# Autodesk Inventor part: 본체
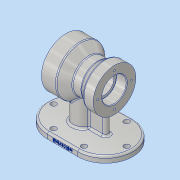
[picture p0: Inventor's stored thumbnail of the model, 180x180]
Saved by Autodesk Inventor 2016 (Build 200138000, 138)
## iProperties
Created: 2020-01
Part Number: 본체
Material: 알루미늄 6061
Document SubType Name: Modeling
Designer: woori
Density: 2.7 g/cm^3
Appearance: 알루미늄 - 평지
Mass: 934.233 g
Surface Area: 654.734 cm^2
Volume: 346.012 cm^3
Author: woori
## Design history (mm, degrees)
sketch "스케치3"
  geometry: L1 (-70, 0)-(-25, 0); L2 (-25, 0)-(25, 0); L3 (25, 0)-(70, 0); L4 (-70, 0)-(-70, 10); L5 (-70, 10)-(70, 10); L6 (70, 10)-(70, 0); 2 further points
  constraints: 12 end point, 2 perpendicular, 2 point on line, 1 coincident, 1 horizontal, 1 midpoint, 1 vertical
  dimensions: "d10" = 45 distance of L1.start L1.end; "d11" = 50 distance of L1.end L2.end; "d12" = 45 distance of L2.end L3.end; "d13" = 10 distance of L1.start L4.end
extrude "돌출1" new body sketch "스케치3" stored distance "d14" = 90; taper "d15" = 0 deg
fillet "모깎기1" dims "d16" = 45
sketch "스케치4"
  geometry: L1 (-40, 80)-(143.887, 80); L2 (-40, 80)-(-40, 120); L3 (-40, 120)-(-16, 120); L4 (40, 115)-(40, 80); L5 (24, 115)-(40, 115); L6 (40, 115)-(40, 80); L7 (-40, 120)-(-16, 120); L8 (-61.291, 80)-(69.038, 80); L9 (-16, 120)-(-1.103, 107.5); L10 (-16, 120)-(3.447, 120); L11 (24, 115)-(44.887, 115); L12 (24, 115)-(13.289, 107.5); L13 (-1.103, 107.5)-(13.289, 107.5); L14 (-25, 0)-(-25, 0) reference; L15 (-25, 0)-(-25, 10) reference; L16 (-25, 10)-(-25, 10) reference; L17 (-25, 10)-(-25, 0) reference; L18 (-70, 10)-(-70, 0) reference; L19 (-70, 10)-(-70, 0) reference; L20 (-70, 10)-(-70, 0) reference; L21 (-25, 0)-(25, 0) reference; 1 further point
  constraints: 26 end point, 4 horizontal, 2 point on line, 1 equal length, 1 parallel, 1 vertical
  dimensions: "d22" = 24 distance of L3.end L2.end; "d25" = 40 deg angle of L9 L10; "d27" = 145 deg angle of L13 L12; "d31" = 30 distance between parallel lines of L18 L2; "d32" = 80 distance between parallel lines of L21 L1; "d33" = 80 distance between parallel lines of L4 L2; "d34" = 16 distance of L5.start L4.start; "d35" = 55 diameter of L13 L1; "d37" = 70 diameter of L5 L1; "d38" = 80 diameter of L3 L1
revolve "회전1" sketch "스케치4" stored, may be unused: angle "d29" = 90 deg
sketch "스케치5"
  geometry: L1 (-49.461, 80)-(59.544, 80); L2 (-40, 40)-(-40, 120) reference; L3 (-40, 80)-(-20, 80); L4 (-20, 80)-(-20, 106); L5 (-20, 106)-(-40, 106); L6 (-40, 106)-(-40, 80); L7 (-20, 80)-(23, 80); L8 (23, 80)-(23, 96); L9 (23, 96)-(-20, 96); L10 (-20, 96)-(-20, 80); L11 (40, 45)-(40, 115) reference; L12 (40, 80)-(23, 80); L13 (23, 80)-(23, 100); L14 (23, 100)-(40, 100); L15 (40, 100)-(40, 80); L16 (-40, 120)-(-16, 120) reference; L17 (-40, 40)-(-16, 40) reference; L18 (24, 115)-(40, 115) reference; L19 (24, 45)-(40, 45) reference; L20 (70, 0)-(25, 0) reference; 1 further point
  constraints: 26 end point, 6 parallel, 4 horizontal, 3 perpendicular, 2 midpoint, 1 point on line
  dimensions: "d39" = 20 distance of L5.end L4.end; "d41" = 52 diameter of L5 L1; "d43" = 17 distance of L13.end L14.end; "d45" = 40 diameter of L14 L1; "d46" = 32 diameter of L9 L1; "d47" = 80 distance between parallel lines of L20 L1
revolve "회전2" sketch "스케치5" stored, may be unused: angle "d48" = 90 deg
chamfer "모따기1" distance "d49" = 1; stored, may be unused: second distance "d50" = 2, angle "d51" = 45 deg
chamfer "모따기2" distance "d52" = 1; stored, may be unused: second distance "d53" = 2, angle "d54" = 45 deg
fillet "모깎기2" dims "d55" = 0.3
fillet "모깎기3" dims "d56" = 0.3
sketch "스케치6" dims "d57" = 66
  geometry: L1 (45, -80)-(-45, -80) reference; 3 further points
  constraints: 3 vertical alignment, 2 other
  dimensions: "d58" = 80 distance from line of L1 point (0, 0)
hole "구멍1" sketch "스케치6" at (0, 33) diameter "d59" = 3.242; stored, may be unused: countersink angle "d63" = 90 deg, drill point angle "d65" = 118 deg; dims "d60" = 9, "d61" = 4, "d62" = 2, "d64" = 11
sketch "스케치7" dims "d69" = 55
  geometry: L1 (45, -80)-(-45, -80) reference; 4 further points
  constraints: 3 vertical alignment, 1 midpoint, 2 other
  dimensions: "d70" = 80 distance from line of L1 point (0, 0)
hole "구멍2" sketch "스케치7" at (0, 27.5) diameter "d71" = 3.242; stored, may be unused: countersink angle "d75" = 90 deg, drill point angle "d77" = 118 deg; dims "d72" = 9, "d73" = 4, "d74" = 2, "d76" = 11
sketch "스케치8"
  geometry: L1 (50, 45)-(25.196, 45); L2 (50, 50)-(25.196, 50); L3 (25.196, 40)-(50, 40); C1 r 16 at (13, 45); A1 r 45 centre (0, 45) between (0, 90) and (0, 0) reference; A2 r 5 centre (50, 45) between (50, 40) and (50, 50); A3 r 5 centre (25.196, 45) between (25.196, 50) and (25.196, 40); 3 further points
  constraints: 8 end point, 5 point on circle, 4 tangent, 3 centre point, 2 horizontal alignment, 1 horizontal, 1 midpoint, 1 parallel
  dimensions: "d81" = 32 diameter of C1; "d82" = 58 distance of C1.centre point (-45, 45); "d83" = 50 distance of L1.start A1.centre; "d84" = 10 distance between parallel lines of L3 L2
extrude "돌출2" join sketch "스케치8" stored distance "d85" = 90; taper "d86" = 0 deg
fillet "모깎기4" dims "d87" = 3
fillet "모깎기5" dims "d88" = 3
fillet "모깎기6" dims "d89" = 3
sketch "스케치9"
  geometry: L1 (50, -77)-(0, -77); L2 (50, -7)-(0, -7); A1 r 45 centre (50, -42) between (50, -87) and (50, 3) reference; A2 r 35 centre (50, -42) between (50, -7) and (50, -77); A3 r 35 centre (0, -42) between (0, -77) and (0, -7); 6 further points
  constraints: 6 point on circle, 4 coincident, 4 end point, 2 centre point, 2 tangent
  dimensions: "d90" = 70 diameter of A2; "d91" = 70 diameter of A3; "d92" = 50 distance of A3.centre A2.centre
hole "구멍3" sketch "스케치9" at (50, -7), (50, -77), (0, -77), (85, -42), (0, -7), (-35, -42) diameter "d93" = 9; stored, may be unused: countersink angle "d97" = 90 deg, drill point angle "d99" = 118 deg; dims "d94" = 9, "d95" = 4, "d96" = 2, "d98" = 11
sketch "스케치10"
  geometry: L1 (-70, 7)-(-70, 0) reference; L2 (70, 0)-(25, 0) reference; 2 further points
  constraints: 1 other
  dimensions: "d100" = 70 distance from line of point (0, 4) L1; "d101" = 4 distance from line of L2 point (0, 4)
feature "엠보싱1" sketch "스케치10" dims "d10" = 45, "d11" = 50, "d12" = 45, "d13" = 10, "d22" = 24, "d25" = 40 deg, "d27" = 145 deg, "d31" = 30, "d32" = 80, "d33" = 80, "d34" = 16, "d35" = 55, "d37" = 70, "d38" = 80, "d102" = 0.5, "d103" = 0
node "솔리드1"
pattern_circular "원형 패턴1" dims angle "d67" = 360 deg
pattern_circular "원형 패턴2" dims angle "d79" = 360 deg
node "투영된 루프1"
other parameters: "d24" = 27.5
